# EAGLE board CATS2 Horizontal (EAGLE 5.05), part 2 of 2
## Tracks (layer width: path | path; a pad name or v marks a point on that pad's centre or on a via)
+5V  (via drill 0.51)
  Top 0.18: v86,58 85.73,57.73 IC49.3 85.73,52.73 84,51 79,51 78,50 78,43 74,39 68,39 | v382,58 384.95,58 R56.2 | IC13.3 373.73,57.73 v374,58 | R40.2 354.95,58.05 v355,58 | IC9.3 347.73,57.73 v348,58 | 332.26,56 IC7.6 | 332.26,56 332.26,57.74 v332,58 | IC7.8 327.18,55.18 328,56 332.26,56 | R67.2 309.95,58.05 v310,58 | IC17.3 301.73,57.73 v302,58 | R82.2 282.95,58.05 v283,58 | IC21.3 274.73,57.73 v275,58 | R97.2 255.95,58.05 v256,58 | IC25.3 247.73,57.73 v248,58 | R112.2 228.95,58.05 v229,58 | IC29.3 220.73,57.73 v221,58 | R127.2 201.95,58.05 v202,58 | IC33.3 193.73,57.73 v194,58 | R142.2 174.95,58.05 v175,58 | IC37.3 166.73,57.73 v167,58 | R157.2 147.95,58.05 v148,58 | IC41.3 139.73,57.73 v140,58 | R172.2 120.95,58.05 v121,58 | IC45.3 112.73,57.73 v113,58 | R187.2 94.05,58.05 v94,58 | 30,98.05 C19.2 | 30,98.05 R27.2 | 30,98.05 30.05,98 IC5.2 30.87,90.13 33,88 v45,88 | IC2.6 55.27,39.73 56,39 68,39 | 68,39 v69,39
  Bottom 0.18: v86,58 v94,58 v113,58 v121,58 v140,58 v148,58 v167,58 v175,58 v194,58 v202,58 v221,58 v229,58 v248,58 v256,58 v275,58 v283,58 v302,58 v310,58 v332,58 v348,58 v355,58 v374,58 v382,58 | v45,88 69,64 v69,39
+12V  (via drill 0.71)
  Top 0.4: R62.1 368,99 367,100 v367,107 | R195.1 80,99 79,100 | 79,100 v79,107 | R180.1 107,99 106,100 v106,107 | R165.1 134,99 133,100 v133,107 | R150.1 161,99 160,100 v160,107 | R135.1 188,99 187,100 v187,107 | R120.1 215,99 214,100 v214,107 | R105.1 242,99 241,100 v241,107 | R90.1 269,99 268,100 v268,107 | R75.1 296,99 295,100 v295,107 | R47.1 337,99 336,100 v336,107 | 82.24,65.19 C95.1 84.95,64.95 IC50.8 | IC46.8 109.24,65.19 C88.1 | IC34.8 190.24,65.19 C67.1 | IC30.8 217.24,65.19 C60.1 | IC26.8 244.24,65.19 C53.1 | IC22.8 271.24,65.19 C46.1 | IC18.8 298.24,65.19 C39.1 | IC10.8 343.24,65.19 C30.1 | IC14.8 370.24,65.19 C38.1 | C74.1 165.95,64.95 IC38.8 | C81.1 138.95,64.95 IC42.8 | v79,91 79,100 | 73.86,45.24 C9.1 72.69,46.31 72,47 v67,47 | 73.86,45.24 PWR1.+VIN | 42,70 42,74 41,75 R18.2 41,74.95 41,74 40.73,73.73 IC4.3 34.27,73.73 | 42,70 R19.2 | C16.1 32.05,70.6 IC4.16 | IC4.16 31.19,71.19 30,70 28,70 27,71 27,71.95 R20.2 | Q3.3 Q4.3 25,77.73 25,76 | 25,76 29,76 30,75 IC4.13 33,75 34.27,73.73 | IC4.16 33.19,71.19 34,72 34,73.46 34.27,73.73 | C17.1 PWR2.+VIN | C17.1 | D3.3 25.07,112.8 C15.POS F1.1A 22,108 25,105 | 25,105 25,99 26,98 26.05,98.05 C18.1 27,96.25 IC5.3 27.54,95.54 26,94 26,87 24,85 19,85 18,84 18,75 | C17.1 26.05,106.05 25,105 | RLY1.3 7.19,76.81 9,75 18,75 | 18,75 24,75 25,76 | AUD2.+ 27.62,32.62 35,40 41.95,40 R8.2 42,43.95 R5.2 v44,44 | 73.86,45.24 73.86,60.86 v78,65 | 53,47.95 53.05,47.95 v54,47 | 53,47.95 C12.1 | 42,70 42,65 v43,64 | v46,64 R24.2 | 51.27,51.27 IC3.8 51.3,51 54,51 54,48.95 53,47.95
  Bottom 0.4: v79,107 v106,107 v133,107 v160,107 v187,107 v214,107 v241,107 v268,107 v295,107 v336,107 v367,107 | 301,64 300,63 275,63 274.19,63.81 IC22.8 274,65 274,64 273,63 248,63 247.19,63.81 IC26.8 247,65 247,64 246,63 221,63 220.19,63.81 IC30.8 220,65 220,64 219,63 194,63 193.19,63.81 IC34.8 193,65 193,64 192,63 167,63 166.19,63.81 IC38.8 166,65 166,64 165,63 140,63 139.19,63.81 IC42.8 139,65 139,64 138,63 113,63 112.19,63.81 IC46.8 112,65 112,64 111,63 86,63 85.19,63.81 IC50.8 80.81,65.19 79.5,66.5 | 301,64 301,65 IC18.8 | 301,64 302,63 345,63 346.19,64.19 IC10.8 346.19,63.81 347,63 372,63 373,64 373,65 IC14.8 | 79.5,66.5 79,67 v79,91 | 79.5,66.5 v78,65 | v67,47 v54,47 54,45 53,44 v44,44 43,45 v43,64 v46,64
+12VA  (via drill 0.71)
  Top 0.4: IC48.8 96.81,32.95 C98.1 95.95,33 95,33 v94,32 94,30.5 89.5,26 PWR1.+VOUT 75.08,24.42 76,23.5 C6.POS 72.75,22.2 R4.1 71.95,16.95 70,15 62,15 v55.5,21.5 | IC44.8 123.81,32.95 C91.1 121.95,32.95 v121,32 | IC40.8 150.81,32.95 C84.1 148.95,32.95 v148,32 | IC36.8 177.81,32.95 C77.1 175.95,32.95 v175,32 | IC32.8 204.81,32.95 C70.1 202.95,32.95 v202,32 | IC28.8 231.81,32.95 C63.1 229.95,32.95 v229,32 | IC24.8 258.81,32.95 C56.1 256.95,32.95 v256,32 | IC20.8 285.81,32.95 C49.1 283.95,32.95 v283,32 | IC16.8 312.81,32.95 C42.1 310.95,32.95 v310,32 | IC6.8 359.81,32.95 C25.1 357.95,32.95 v357,32 | IC11.8 384.81,32.95 C33.1 382.95,32.95 v382,32 | C4.1 44.09,20 IC1.5 44.37,20.86 45,21.5 v50,21.5
  Bottom 0.4: v94,32 v121,32 v148,32 v175,32 v202,32 v229,32 v256,32 v283,32 v310,32 v357,32 v382,32 | v55.5,21.5 v50,21.5
+12VB  (via drill 0.51)
  Top 0.18: v86,40 85.73,40.27 IC49.6 85.73,45.27 85,46 82,46 79.75,43.75 79.75,34 77,34 70.05,27.05 R4.2 66.8,23 C3.POS 65.8,22 64,22 59,27 59,32 56,32 55.27,31.27 IC2.3 | v389,40 389,42.73 IC12.3 | IC45.6 112.73,40.27 v113,40 | IC41.6 139.73,40.27 v140,40 | IC37.6 166.73,40.27 v167,40 | IC33.6 193.73,40.27 v194,40 | IC29.6 220.73,40.27 v221,40 | IC47.3 101.27,40.27 v101,40 | IC43.3 128.27,40.27 v128,40 | IC39.3 155.27,40.27 v155,40 | IC35.3 182.27,40.27 v182,40 | IC31.3 209.27,40.27 v209,40 | IC27.3 236.27,40.27 v236,40 | IC25.6 247.73,40.27 v248,40 | IC23.3 263.27,40.27 v263,40 | IC21.6 274.73,40.27 v275,40 | IC19.3 290.27,40.27 v290,40 | IC17.6 301.73,40.27 v302,40 | IC15.3 317.27,40.27 v317,40 | IC9.6 347.73,40.27 v348,40 | IC8.3 362.27,40.27 v362,40 | IC13.6 373.73,40.27 v374,40
  Bottom 0.18: v86,40 v101,40 v113,40 v128,40 v140,40 v155,40 v167,40 v182,40 v194,40 v209,40 v221,40 v236,40 v248,40 v263,40 v275,40 v290,40 v302,40 v317,40 v348,40 v362,40 v374,40 v389,40
+15V  (via drill 0.71)
  Top 0.4: C20.POS 71,108.55 PWR2.+VOUT 73.5,104.5 v74,104
  Bottom 0.4: J36.1 J33.1 J30.1 J27.1 J24.1 J21.1 J18.1 J15.1 J9.1 J12.1 | J39.1 92.9,94.5 76.5,94.5 74,97 v74,104
  Bottom 0.406: J36.1 J39.1
-8V  (via drill 0.51)
  Top 0.18: v367,55 IC8.5 | v322,55 IC15.5 | v295,55 IC19.5 | v268,55 IC23.5 | v241,55 IC27.5 | IC31.5 v214,55 | v187,55 IC35.5 | v160,55 IC39.5 | v133,55 IC43.5 | v106,55 IC47.5 103.81,113.19 100.75,116.25 77.75,116.25 75,119 59,119 57,117 57,114.09 D5.1 R28.1 55,111 54.2,111.8 C22.POS | IC12.5 392,54.81 v392,52
  Bottom 0.18: v392,52 392,54 391,55 v367,55 v322,55 v295,55 v268,55 v241,55 v214,55 v187,55 v160,55 v133,55 v106,55
-15V  (via drill 0.71)
  Top 0.4: PWR2.-VOUT 73.19,90.81 70,94 70,97.47 PWR2.TRM | C21.NEG 64,116 62,114 62,112 61,111 | 61,111 R28.2 | PWR2.TRM 70.03,100.97 61,110 61,111 | v76,99 75.47,99 PWR2.TRM
  Bottom 0.4: v76,99 77.74,97.26 J39.2 J36.2 J33.2 J30.2 J27.2 J24.2 J21.2 J18.2 J15.2 J9.2 J12.2
AGND
  pour Top (rank 2): 7,0 32,0 32,28 46,28 46,36 78.5,36 78.5,49 395,49 395,121 0,121 0,75 4,75 4,56 7,56
  pour Bottom (rank 2): 0,0 32,0 32,28 46,28 46,36 78.5,36 78.5,49 395,49 395,121 0,121
DRIVE  (via drill 0.51)
  Top 0.18: v101,81 D38.3 | v389,79 D10.3 | v362,81 D8.3 | v317,81 D14.3 | v290,81 D17.3 | v263,81 D20.3 | v236,81 D23.3 | v209,81 D26.3 | v182,81 D29.3 | v155,81 D32.3 | v128,81 D35.3 | D2.3 46.73,70.73 v57,81 v89,81
  Bottom 0.18: v389,79 387,81 v362,81 v317,81 v290,81 v263,81 v236,81 v209,81 v182,81 v155,81 v128,81 v101,81 v89,81 | J4.7 11.63,103.37 19,96 42,96 v57,81
GND
  pour Top: 33,0 395,0 395,48 79.5,48 79.5,35 47,35 47,27 33,27
  pour Bottom: 33,0 395,0 395,48 79.5,48 79.5,35 47,35 47,27 33,27
N$1
  Top 0.18: R21.1 R23.2 54,61.05 54,62 52.05,63.95 Q2.1
N$2
  Top 0.18: IC3.1 51.27,57.27 52,58 52,58.95 | 52,58.95 R21.2 | 52,58.95 50,58.95 C11.2
N$3
  Top 0.18: Q5.1 57.17,61 56,61 55,62 55,66 54.73,66.27 Q2.3 51.27,66.27 50,65 50,64.05 R24.1
N$4
  Top 0.18: R22.2 47,67 45,65 45,63 47,61 R15.2 C11.1 48,58.95 48,58 50,56 IC3.2
N$5
  Top 0.18: J9.6 340.38,95.89 D9.3
N$6
  Top 0.18: R47.2 347.21,99 J9.7
N$7
  Top 0.18: D7.1 339.05,103.95 341,102 341,101.05 R48.2 347.21,101 J9.8
N$8
  Top 0.18: J5.CONDUCTOR 22,9 21,8 R30.1
N$9
  Top 0.18: D3.1 28.05,116.95 29,116 29,111.27 D4.3
N$10
  Top 0.18: D2.1 45.95,75 R16.2
N$11
  Top 0.18: Q1.3 39.73,76.73 39,76 | 39,76 39,75.05 R18.1 | IC4.11 33.46,77.54 34.73,76.27 IC4.5 38.73,76.27 39,76
N$12
  Top 0.18: IC4.6 35.46,77.54 34,79 34,80 33,81 27,81 Q3.1
N$13
  Top 0.18: R20.1 C14.2 29.22,73.73 IC4.14
N$14
  Top 0.18: IC4.2 38.59,72.46 C13.2 R19.1
N$15
  Top 0.18: Q4.1 28.05,77.05 29.81,78.81 IC4.10
N$16  (via drill 0.51)
  Top 0.18: Q4.2 27.95,78.95 v29,80
  Bottom 0.18: v29,80 12,63 12,56.72 AUD1.+
N$17
  Top 0.18: R25.1 21.05,79.59 TP.1
N$18
  Top 0.18: Q3.2 23,82.95 R25.2
N$19
  Top 0.18: J2.CONDUCTOR R7.1
N$20  (via drill 0.51)
  Top 0.18: 7.19,82.81 RLY1.1 7.11,82 5,82 | J4.3 7,102 1,96 1,86 5,82 | Q5.2 60,65.92 60,67 59,68 51,68 50,67 R22.1 49.95,68.05 49,69 47,69 44,66 44,63 43,62 42,62 37,67 v7,67 | v3,81 4,81 5,82
  Bottom 0.18: v7,67 7,77 v3,81
N$21
  Top 0.18: J12.5 382.52,105.48 388,100 388,82 384,78 384,76.05 R61.1
N$22
  Top 0.18: IC8.6 362,55.27 C27.2 R41.2
N$23
  Top 0.18: IC14.1 382.07,65.19 R199.CW 388.66,62.46 R199.W 391.2,65.8 388,69 388,70 D10.1 388,70.09 388,71 385.95,73.05 R61.2
N$24
  Top 0.18: R16.1 R17.2 42.05,76.95 Q1.1
N$25  (via drill 0.51)
  Top 0.18: C37.1 383,70 380.81,67.81 IC14.2 380.54,68 379,68 | R57.1 R56.1 383.05,59.95 378,65 378,67 379,68 | R58.2 377.95,69.05 379,68 | v374,78 R59.2
  Bottom 0.18: v374,78 375.95,78 R58.2 377.95,69.05 379,68 380.54,68 IC14.2
N$26
  Top 0.18: J12.3 383,100 387,96 387,84 386,83 381,83 376,78 376,76.05 R58.1 373.19,73.14 IC14.5 371,75 C102.2
N$27
  Top 0.18: R199.CCW 384.7,67.7 386,69 386,69.95 C37.2
N$28
  Top 0.18: C34.2 385.73,25.32 IC11.1 385.73,29.73 386.25,30.25 390.25,30.25 391,31 391,35 387,39 387,42.73 IC12.2
N$29
  Top 0.18: R29.2 17.05,5.05 D6.1 17,5 17,6 Q6.1
N$30
  Top 0.18: R26.2 33,96.25 IC5.1
N$31
  Bottom 0.4: F1.2A 22,88 12,98 10.53,98 J4.9
N$32
  Top 0.18: J15.5 310.52,105.48 316,100 316,82 312,78 312,76.05 R64.1
N$33
  Top 0.18: J10.CONDUCTOR R49.2
N$34
  Top 0.18: R49.1 R51.2 C32.2 380.05,15 381,15 389,23 389,26 388.27,26.73 IC11.3
N$35
  Top 0.18: R52.2 392,42.81 IC12.4 | C34.1 387.95,26.05 387,27 IC11.2 387,29 387.75,29.75 393.75,29.75 394,30 394,39 393,40 392.05,40 R52.2 | R52.2 391.95,40
N$36
  Top 0.18: C36.2 370.32,67.73 IC14.7 373.46,68 375,68 376,67 R55.2
N$37
  Top 0.18: R55.1 376,55.27 IC13.2
N$38
  Top 0.18: IC14.6 370.32,70.27 C36.1 369.95,69.95 368.25,68.25 368.25,59.75 370,58 370.95,58 R60.2 371,55.19 IC13.4
N$39
  Top 0.18: IC13.5 371.19,40.14 R54.2 371,39.95 372.05,39.95 376,36 388,36 389.54,34.46 IC11.5
N$40
  Top 0.18: R50.1 376,34 377,35 386,35 387,34 IC11.7 IC11.6
N$41
  Top 0.18: Q6.3 13,8 9,12 9,27.62 AUD2.-
N$42
  Top 0.18: J11.CONDUCTOR R50.2
N$43
  Top 0.18: J9.5 351.52,105.48 357,100 357,76.05 R46.1
N$44
  Top 0.18: R46.2 358.95,73.05 361,71 361,70.09 D8.1 361.05,68.95 364,66 364,65.2 R45.W 360.34,65 R45.CW 356.54,62.46 IC10.1
N$45  (via drill 0.51)
  Top 0.18: C29.1 356,70 353.81,67.81 IC10.2 352,67.73 | R41.1 R40.1 356.05,59.95 355,61 | 352,67.73 351.27,67.73 350,69 350,75.95 R42.2 | 355,61 351,65 351,66.73 352,67.73 | v346,77 R43.2 | R39.1 335.95,58.95 v338,61 | v353,61 355,61
  Bottom 0.18: v346,77 348.95,77 R42.2 349.95,69.05 351,68 353.54,68 IC10.2 | v338,61 v353,61
N$46
  Top 0.18: J9.3 352,100 356,96 356,84 355,83 353,83 348,78 348,76.05 R42.1 346.19,74.14 IC10.5 345,74 C31.2
N$47
  Top 0.18: C29.2 358.95,68.79 R45.CCW
N$48
  Top 0.18: D1.1 58.95,52.51 J3.1
N$49
  Top 0.18: R14.2 C10.2 R13.2 61,47 58,44 | IC2.5 57.81,43.81 58,44 | IC3.3 48.73,53.27 49,53 54,53 55,52 55,47 58,44
N$50
  Top 0.18: R10.2 C2.2 51,17.25 50.5,16.75 48.5,16.75 47.25,18 47.25,18.25 46.75,18.75 44.75,18.75 44.5,18.5 44.5,17.86 IC1.1
N$51
  Top 0.18: R10.1 53,29 52.73,29.27 IC2.2
N$52
  Top 0.18: J1.CONDUCTOR R1.2
N$53
  Top 0.18: R1.1 R2.2 C1.2 46.27,15.22 IC1.3
N$54
  Top 0.18: IC1.4 46.29,20.25 48,20.25 48.3,19.95 R3.2 C2.1 51,21 51.5,21.5 51.5,32 54,32 54,28 57,28 57.81,28.81 IC2.4
N$55
  Top 0.18: C26.2 360.73,25.32 IC6.1 360.73,29.73 361.25,30.25 365.25,30.25 366,31 366,34 362,38 361,38 360,39 360,42.73 IC8.2
N$56
  Top 0.18: C31.1 R43.1
N$57
  Top 0.18: J7.CONDUCTOR R32.2
N$58
  Top 0.18: R32.1 R34.2 C24.2 355.05,15 356,15 364,23 364,26 363.27,26.73 IC6.3
N$59
  Top 0.18: R35.2 365,42.81 IC8.4 | C26.1 362.95,26.05 362,27 IC6.2 362,29 362.75,29.75 366.75,29.75 367,30 367,39 366,40 365.05,40 R35.2 | R35.2 364.95,40
N$60
  Top 0.18: R6.W 45.85,47.8 C5.2 46,49 47.46,50.46 IC3.5
N$61
  Top 0.18: C28.2 343.95,69.05 345,68 345.92,68 IC10.7 346.46,68 348,68 350,66 R38.2
N$62
  Top 0.18: IC9.2 350.27,57.78 R38.1
N$63
  Top 0.18: IC10.6 345.92,70 345,70 344.05,70.95 C28.1 342.95,71 342,71 341,70 341,61 344,58 344.05,58.05 R44.2 345,55.19 IC9.4
N$64
  Top 0.18: IC9.5 345.19,40.14 R37.2 345,39.95 346.05,39.95 350,36 363,36 364.54,34.46 IC6.5
N$65
  Top 0.18: R33.1 351,34 352,35 361,35 362,34 IC6.7 IC6.6
N$66
  Top 0.18: J8.CONDUCTOR R33.2
N$67
  Top 0.18: R31.2 330,31 J6.CONDUCTOR
N$68
  Top 0.18: R31.1 330,44.33 IC7.2
N$69
  Top 0.18: IC7.3 332.26,32.74 333,32 333,30.54 J6.SHIELD1 333.5,29.96 333.5,29 333,28.5 329,28.5 328.46,29.04 J6.SHIELD2
N$70
  Top 0.18: R6.CW 38.46,45.59 R5.1
N$71
  Top 0.18: R39.2 335,53.83 IC7.5
N$72  (via drill 0.51)
  Top 0.18: 50,49.25 50,48.05 C7.1 R11.2 | 50,49.25 IC3.7 | v53,50 52.25,49.25 50,49.25
  Bottom 0.18: J3.2 57,56 53,52 v53,50
N$73
  Top 0.18: J12.6 371.38,95.89 D12.3
N$74
  Top 0.18: R62.2 378.21,99 J12.7
N$75
  Top 0.18: D11.1 370.05,103.95 372,102 372,101.05 R63.2 378.21,101 J12.8
N$76
  Top 0.18: R57.2 C35.2 389,55.27 IC12.6
N$77
  Top 0.18: R13.1 60.05,49.95 60,50 59,49 58.27,49 D1.3
N$78
  Top 0.18: IC3.6 48.73,49.73 48,49 48,48.05 C7.2 R11.1 48,45.95 48,45 44,41 R9.1
N$79
  Top 0.18: R36.2 357,42.81 IC8.1
N$80
  Top 0.18: R53.2 384,42.81 IC12.1
N$81  (via drill 0.51)
  Top 0.18: IC18.1 311.86,65.19 R66.1 | R64.2 313.95,71.05 315,70 316,70 | 316,70 D14.1 | v316,68 316,70
  Bottom 0.18: v316,68 313.19,65.19 IC18.1
N$82  (via drill 0.51)
  Top 0.18: C40.1 309.08,68 IC18.2 307.27,67.73 | R77.1 R67.1 311.05,59.95 306,65 306,66.46 307.27,67.73 | 307.27,67.73 306,69 306,75.95 R65.2 | v302,79 R200.2
  Bottom 0.18: v302,79 302.95,79 R65.2 305.95,69.05 307,68 308.54,68 IC18.2
N$83
  Top 0.18: J15.3 311,100 315,96 315,84 314,83 309,83 304,78 304,76.05 R65.1 301.19,73.14 IC18.5 298.95,75.05 C103.2
N$84
  Top 0.18: R66.2 C40.2
N$85
  Top 0.18: C43.2 313.73,25.32 IC16.1 313.73,29.73 314.25,30.25 318.25,30.25 319,31 319,35 315,39 315,42.73 IC15.2
N$86
  Top 0.18: J14.CONDUCTOR R68.2
N$87
  Top 0.18: R68.1 R69.2 C45.2 308.05,15 309,15 317,23 317,26 316.27,26.73 IC16.3
N$88
  Top 0.18: R70.2 320,42.81 IC15.4 | C43.1 315.95,26.05 315,27 IC16.2 315,29 315.75,29.75 321.75,29.75 322,30 322,39 321,40 320.05,40 R70.2 | R70.2 319.95,40
N$89
  Top 0.18: C44.2 298.32,67.73 IC18.7 301.46,68 303,68 304,67 R71.2
N$90
  Top 0.18: R71.1 304,55.27 IC17.2
N$91
  Top 0.18: IC18.6 298.32,70.27 C44.1 297.95,69.95 296.25,68.25 296.25,59.75 298,58 298.95,58 R72.2 299,55.19 IC17.4
N$92
  Top 0.18: IC17.5 299.19,40.14 R73.2 299,39.95 300.05,39.95 304,36 316,36 317.54,34.46 IC16.5
N$93
  Top 0.18: R74.1 304,34 305,35 314,35 315,34 IC16.7 IC16.6
N$94
  Top 0.18: J13.CONDUCTOR R74.2
N$95
  Top 0.18: D13.3 306.2,96.27 J15.6
N$96
  Top 0.18: R75.2 306.21,99 J15.7
N$97
  Top 0.18: D15.1 298.05,103.95 300,102 300,101.05 R76.2 306.21,101 J15.8
N$98
  Top 0.18: IC15.6 317.27,57.78 C41.2 R77.2
N$99
  Top 0.18: R78.2 312,42.81 IC15.1
N$100
  Top 0.18: J18.5 283.52,105.48 289,100 289,82 285,78 285,76.05 R79.1
N$101  (via drill 0.51)
  Top 0.18: IC22.1 284.86,65.19 R81.1 | R79.2 286.95,71.05 288,70 289,70 | 289,70 D17.1 | v289,68 289,70
  Bottom 0.18: v289,68 286.19,65.19 IC22.1
N$102  (via drill 0.51)
  Top 0.18: C47.1 284.78,67.73 IC22.2 280.27,67.73 | R92.1 R82.1 284.05,59.95 279,65 279,66.46 280.27,67.73 | 280.27,67.73 279,69 279,75.95 R80.2 | v275,79 R201.2
  Bottom 0.18: v275,79 275.95,79 R80.2 278.95,69.05 280,68 281.54,68 IC22.2
N$103
  Top 0.18: J18.3 284,100 288,96 288,84 287,83 282,83 277,78 277,76.05 R80.1 274.19,73.14 IC22.5 271.95,75.05 C104.2
N$104
  Top 0.18: R81.2 C47.2
N$105
  Top 0.18: C50.2 286.73,25.32 IC20.1 286.73,29.73 287.25,30.25 291.25,30.25 292,31 292,35 288,39 288,42.73 IC19.2
N$106
  Top 0.18: J17.CONDUCTOR R83.2
N$107
  Top 0.18: R83.1 R84.2 C52.2 281.05,15 282,15 290,23 290,26 289.27,26.73 IC20.3
N$108
  Top 0.18: R85.2 293,42.81 IC19.4 | C50.1 288.95,26.05 288,27 IC20.2 288,29 288.75,29.75 294.75,29.75 295,30 295,39 294,40 293.05,40 R85.2 | R85.2 292.95,40
N$109
  Top 0.18: C51.2 271.32,67.73 IC22.7 274.46,68 276,68 277,67 R86.2
N$110
  Top 0.18: IC21.2 277.27,57.78 R86.1
N$111
  Top 0.18: IC22.6 271.32,70.27 C51.1 270.95,69.95 269.25,68.25 269.25,59.75 271,58 271.95,58 R87.2 272.19,57.86 IC21.4
N$112
  Top 0.18: IC21.5 272.19,40.14 R88.2 272,39.95 273.05,39.95 277,36 289,36 290.54,34.46 IC20.5
N$113
  Top 0.18: R89.1 277,34 278,35 287,35 288,34 IC20.7 IC20.6
N$114
  Top 0.18: J16.CONDUCTOR R89.2
N$115
  Top 0.18: D16.3 279.2,96.27 J18.6
N$116
  Top 0.18: R90.2 279.21,99 J18.7
N$117
  Top 0.18: D18.1 271.05,103.95 273,102 273,101.05 R91.2 279.21,101 J18.8
N$118
  Top 0.18: IC19.6 290.27,57.78 C48.2 R92.2
N$119
  Top 0.18: R93.2 285,42.81 IC19.1
N$120
  Top 0.18: J21.5 256.52,105.48 262,100 262,82 258,78 258,76.05 R94.1
N$121  (via drill 0.51)
  Top 0.18: IC26.1 257.86,65.19 R96.1 | R94.2 259.95,71.05 261,70 262,70 | 262,70 D20.1 | v262,68 262,70
  Bottom 0.18: v262,68 259.19,65.19 IC26.1
N$122  (via drill 0.51)
  Top 0.18: C54.1 257.78,67.73 IC26.2 253.27,67.73 | R107.1 R97.1 257.05,59.95 252,65 252,66.46 253.27,67.73 | 253.27,67.73 252,69 252,75.95 R95.2 | v248,79 R202.2
  Bottom 0.18: v248,79 248.95,79 R95.2 251.95,69.05 253,68 254.54,68 IC26.2
N$123
  Top 0.18: J21.3 257,100 261,96 261,84 260,83 255,83 250,78 250,76.05 R95.1 247.19,73.14 IC26.5 244.95,75.05 C105.2
N$124
  Top 0.18: R96.2 C54.2
N$125
  Top 0.18: C57.2 259.73,25.32 IC24.1 259.73,29.73 260.25,30.25 264.25,30.25 265,31 265,35 261,39 261,42.73 IC23.2
N$126
  Top 0.18: J20.CONDUCTOR R98.2
N$127
  Top 0.18: R98.1 R99.2 C59.2 254.05,15 255,15 263,23 263,26 262.27,26.73 IC24.3
N$128
  Top 0.18: R100.2 266,42.81 IC23.4 | C57.1 261.95,26.05 261,27 IC24.2 261,29 261.75,29.75 267.75,29.75 268,30 268,39 267,40 266.05,40 R100.2 | R100.2 265.95,40
N$129
  Top 0.18: C58.2 244.32,67.73 IC26.7 247.46,68 249,68 250,67 R101.2
N$130
  Top 0.18: IC25.2 250.27,57.78 R101.1
N$131
  Top 0.18: IC26.6 244.32,70.27 C58.1 243.95,69.95 242.25,68.25 242.25,59.75 244,58 244.95,58 R102.2 245,55.19 IC25.4
N$132
  Top 0.18: IC25.5 245.19,40.14 R103.2 245,39.95 246.05,39.95 250,36 262,36 263.54,34.46 IC24.5
N$133
  Top 0.18: R104.1 250,34 251,35 260,35 261,34 IC24.7 IC24.6
N$134
  Top 0.18: J19.CONDUCTOR R104.2
N$135
  Top 0.18: D19.3 252.2,96.27 J21.6
N$136
  Top 0.18: R105.2 252.21,99 J21.7
N$137
  Top 0.18: D21.1 244.05,103.95 246,102 246,101.05 R106.2 252.21,101 J21.8
N$138
  Top 0.18: IC23.6 263.27,57.78 C55.2 R107.2
N$139
  Top 0.18: R108.2 258,42.81 IC23.1
N$140
  Top 0.18: J24.5 229.52,105.48 235,100 235,82 231,78 231,76.05 R109.1
N$141  (via drill 0.51)
  Top 0.18: IC30.1 230.86,65.19 R111.1 | R109.2 232.95,71.05 234,70 235,70 | 235,70 D23.1 | v235,68 235,70
  Bottom 0.18: v235,68 232.19,65.19 IC30.1
N$142  (via drill 0.51)
  Top 0.18: C61.1 228.08,68 IC30.2 226.27,67.73 | R122.1 R112.1 230.05,59.95 225,65 225,66.46 226.27,67.73 | 226.27,67.73 225,69 225,75.95 R110.2 | v221,79 R203.2
  Bottom 0.18: v221,79 221.95,79 R110.2 224.95,69.05 226,68 227.54,68 IC30.2
N$143
  Top 0.18: J24.3 230,100 234,96 234,84 233,83 228,83 223,78 223,76.05 R110.1 220.19,73.14 IC30.5 217.95,75.05 C106.2
N$144
  Top 0.18: R111.2 C61.2
N$145
  Top 0.18: C64.2 232.73,25.32 IC28.1 232.73,29.73 233.25,30.25 237.25,30.25 238,31 238,35 234,39 234,42.73 IC27.2
N$146
  Top 0.18: J23.CONDUCTOR R113.2
N$147
  Top 0.18: R113.1 R114.2 C66.2 227.05,15 228,15 236,23 236,26 235.27,26.73 IC28.3
N$148
  Top 0.18: R115.2 239,42.81 IC27.4 | C64.1 234.95,26.05 234,27 IC28.2 234,29 234.75,29.75 240.75,29.75 241,30 241,39 240,40 239.05,40 R115.2 | R115.2 238.95,40
N$149
  Top 0.18: C65.2 217.32,67.73 IC30.7 220.46,68 222,68 223,67 R116.2
N$150
  Top 0.18: IC29.2 223.27,57.78 R116.1
N$151
  Top 0.18: IC30.6 217.32,70.27 C65.1 216.95,69.95 215.25,68.25 215.25,59.75 217,58 217.95,58 R117.2 218.19,57.86 IC29.4
N$152
  Top 0.18: IC29.5 218.19,40.14 R118.2 218,39.95 219.05,39.95 223,36 235,36 236.54,34.46 IC28.5
N$153
  Top 0.18: R119.1 223,34 224,35 233,35 234,34 IC28.7 IC28.6
N$154
  Top 0.18: J22.CONDUCTOR R119.2
N$155
  Top 0.18: D22.3 225.2,96.27 J24.6
N$156
  Top 0.18: R120.2 225.21,99 J24.7
N$157
  Top 0.18: D24.1 217.05,103.95 219,102 219,101.05 R121.2 225.21,101 J24.8
N$158
  Top 0.18: IC27.6 236.27,57.78 C62.2 R122.2
N$159
  Top 0.18: R123.2 231,42.81 IC27.1
N$160
  Top 0.18: J27.5 202.52,105.48 208,100 208,82 204,78 204,76.05 R124.1
N$161  (via drill 0.51)
  Top 0.18: IC34.1 203.86,65.19 R126.1 | R124.2 205.95,71.05 207,70 208,70 | 208,70 D26.1 | v208,68 208,70
  Bottom 0.18: v208,68 205.19,65.19 IC34.1
N$162  (via drill 0.51)
  Top 0.18: C68.1 201.08,68 IC34.2 199.27,67.73 | R137.1 R127.1 203.05,59.95 198,65 198,66.46 199.27,67.73 | 199.27,67.73 198,69 198,75.95 R125.2 | v194,79 R205.2
  Bottom 0.18: v194,79 195,79 198,76 198,69 199,68 200.54,68 IC34.2
N$163
  Top 0.18: J27.3 203,100 207,96 207,84 206,83 201,83 196,78 196,76.05 R125.1 193.19,73.14 IC34.5 190.95,75.05 C108.2
N$164
  Top 0.18: R126.2 C68.2
N$165
  Top 0.18: C71.2 205.73,25.32 IC32.1 205.73,29.73 206.25,30.25 210.25,30.25 211,31 211,35 207,39 207,42.73 IC31.2
N$166
  Top 0.18: J26.CONDUCTOR R128.2
N$167
  Top 0.18: R128.1 R129.2 C73.2 200.05,15 201,15 209,23 209,26 208.27,26.73 IC32.3
N$168
  Top 0.18: R130.2 212,42.81 IC31.4 | C71.1 207.95,26.05 207,27 IC32.2 207,29 207.75,29.75 213.75,29.75 214,30 214,39 213,40 212.05,40 R130.2 | R130.2 211.95,40
N$169
  Top 0.18: C72.2 190.32,67.73 IC34.7 193.46,68 195,68 196,67 R131.2
N$170
  Top 0.18: R131.1 196,55.27 IC33.2
N$171
  Top 0.18: IC34.6 190.32,70.27 C72.1 189.95,69.95 188.25,68.25 188.25,59.75 190,58 190.95,58 R132.2 191,55.19 IC33.4
N$172
  Top 0.18: IC33.5 191.19,40.14 R133.2 191,39.95 192.05,39.95 196,36 208,36 209.54,34.46 IC32.5
N$173
  Top 0.18: R134.1 196,34 197,35 206,35 207,34 IC32.7 IC32.6
N$174
  Top 0.18: J25.CONDUCTOR R134.2
N$175
  Top 0.18: D25.3 198.2,96.27 J27.6
N$176
  Top 0.18: R135.2 198.21,99 J27.7
N$177
  Top 0.18: D27.1 190.05,103.95 192,102 192,101.05 R136.2 198.21,101 J27.8
N$178
  Top 0.18: IC31.6 209.27,57.78 C69.2 R137.2
N$179
  Top 0.18: R138.2 204,42.81 IC31.1
N$180
  Top 0.18: J30.5 175.52,105.48 181,100 181,82 177,78 177,76.05 R139.1
N$181  (via drill 0.51)
  Top 0.18: R139.2 178.95,71.05 180,70 181,70 | R141.1 174,65 IC38.1 | 181,70 D29.1 | v181,68 181,70
  Bottom 0.18: v181,68 178.19,65.19 IC38.1
N$182  (via drill 0.51)
  Top 0.18: C75.1 176.78,67.73 IC38.2 172.27,67.73 | R152.1 R142.1 176.05,59.95 171,65 171,66.46 172.27,67.73 | 172.27,67.73 171,69 171,75.95 R140.2 | v167,79 R204.2
  Bottom 0.18: v167,79 167.95,79 R140.2 170.95,69.05 172,68 173.54,68 IC38.2
N$183
  Top 0.18: J30.3 176,100 180,96 180,84 179,83 174,83 169,78 169,76.05 R140.1 166.19,73.14 IC38.5 163.95,75.05 C107.2
N$184
  Top 0.18: R141.2 C75.2
N$185
  Top 0.18: C78.2 178.73,25.32 IC36.1 178.73,29.73 179.25,30.25 183.25,30.25 184,31 184,35 180,39 180,42.73 IC35.2
N$186
  Top 0.18: J29.CONDUCTOR R143.2
N$187
  Top 0.18: R143.1 R144.2 C80.2 173.05,15 174,15 182,23 182,26 181.27,26.73 IC36.3
N$188
  Top 0.18: R145.2 185,42.81 IC35.4 | C78.1 180.95,26.05 180,27 IC36.2 180,29 180.75,29.75 186.75,29.75 187,30 187,39 186,40 185.05,40 R145.2 | R145.2 184.95,40
N$189
  Top 0.18: C79.2 163.32,67.73 IC38.7 166.46,68 168,68 169,67 R146.2
N$190
  Top 0.18: R146.1 169,55.27 IC37.2
N$191
  Top 0.18: IC38.6 163.32,70.27 C79.1 162.95,69.95 161.25,68.25 161.25,59.75 163,58 163.95,58 R147.2 164,55.19 IC37.4
N$192
  Top 0.18: IC37.5 164.19,40.14 R148.2 164,39.95 165.05,39.95 169,36 181,36 182.54,34.46 IC36.5
N$193
  Top 0.18: R149.1 169,34 170,35 179,35 180,34 IC36.7 IC36.6
N$194
  Top 0.18: J28.CONDUCTOR R149.2
N$195
  Top 0.18: D28.3 171.2,96.27 J30.6
N$196
  Top 0.18: R150.2 171.21,99 J30.7
N$197
  Top 0.18: D30.1 163.05,103.95 165,102 165,101.05 R151.2 171.21,101 J30.8
N$198
  Top 0.18: IC35.6 182,55.27 C76.2 R152.2
N$199
  Top 0.18: R153.2 177,42.81 IC35.1
N$200
  Top 0.18: J33.5 148.52,105.48 154,100 154,82 150,78 150,76.05 R154.1
N$201  (via drill 0.51)
  Top 0.18: IC42.1 149.86,65.19 R156.1 | R154.2 151.95,71.05 153,70 154,70 | 154,70 D32.1 | v154,68 154,70
  Bottom 0.18: v154,68 151.19,65.19 IC42.1
N$202  (via drill 0.51)
  Top 0.18: C82.1 147.08,68 IC42.2 145.27,67.73 | R167.1 R157.1 149.05,59.95 144,65 144,66.46 145.27,67.73 | 145.27,67.73 144,69 144,75.95 R155.2 | v140,79 R206.2
  Bottom 0.18: v140,79 140.95,79 R155.2 143.95,69.05 145,68 146.54,68 IC42.2
N$203
  Top 0.18: J33.3 149,100 153,96 153,84 152,83 147,83 142,78 142,76.05 R155.1 139.19,73.14 IC42.5 136.95,75.05 C109.2
N$204
  Top 0.18: R156.2 C82.2
N$205
  Top 0.18: C85.2 151.73,25.32 IC40.1 151.73,29.73 152.25,30.25 156.25,30.25 157,31 157,35 153,39 153,42.73 IC39.2
N$206
  Top 0.18: J32.CONDUCTOR R158.2
N$207
  Top 0.18: R158.1 R159.2 C87.2 146.05,15 147,15 155,23 155,26 154.27,26.73 IC40.3
N$208
  Top 0.18: R160.2 158,42.81 IC39.4 | C85.1 153.95,26.05 153,27 IC40.2 153,29 153.75,29.75 159.75,29.75 160,30 160,39 159,40 158.05,40 R160.2 | R160.2 157.95,40
N$209
  Top 0.18: C86.2 137.95,68.05 138,68 138.92,68 IC42.7 139.46,68 141,68 142,67 R161.2
N$210
  Top 0.18: R161.1 142,55.27 IC41.2
N$211
  Top 0.18: IC42.6 138.87,69.95 C86.1 135.95,69.95 134.25,68.25 134.25,59.75 136,58 136.95,58 R162.2 137,55.19 IC41.4
N$212
  Top 0.18: IC40.5 155.54,34.46 154,36 142,36 138.05,39.95 137.47,39.95 137.19,40.24 | R163.2 137.19,40.24 | 137.19,40.24 IC41.5
N$213
  Top 0.18: R164.1 142,34 143,35 152,35 153,34 IC40.7 IC40.6
N$214
  Top 0.18: J31.CONDUCTOR R164.2
N$215
  Top 0.18: D31.3 144.2,96.27 J33.6
N$216
  Top 0.18: R165.2 144.21,99 J33.7
N$217
  Top 0.18: D33.1 136.05,103.95 138,102 138,101.05 R166.2 144.21,101 J33.8
N$218
  Top 0.18: IC39.6 155.27,57.78 C83.2 R167.2
N$219
  Top 0.18: R168.2 150,42.81 IC39.1
N$220
  Top 0.18: J36.5 121.52,105.48 127,100 127,82 123,78 123,76.05 R169.1
N$221  (via drill 0.51)
  Top 0.18: IC46.1 122.86,65.19 R171.1 | R169.2 124.95,71.05 126,70 127,70 | 127,70 D35.1 | v127,68 127,70
  Bottom 0.18: v127,68 124.19,65.19 IC46.1
N$222  (via drill 0.51)
  Top 0.18: C89.1 122.78,67.73 IC46.2 118.27,67.73 | R182.1 R172.1 122.05,59.95 117,65 117,66.46 118.27,67.73 | 118.27,67.73 117,69 117,75.95 R170.2 | v113,79 R207.2
  Bottom 0.18: v113,79 113.95,79 R170.2 116.95,69.05 118,68 119.54,68 IC46.2
N$223
  Top 0.18: J36.3 122,100 126,96 126,84 125,83 120,83 115,78 115,76.05 R170.1 115.05,75.67 IC46.5 109.95,75.05 C110.2
N$224
  Top 0.18: R171.2 C89.2
N$225
  Top 0.18: C92.2 124.73,25.32 IC44.1 124.73,29.73 125.25,30.25 129.25,30.25 130,31 130,35 126,39 126,42.73 IC43.2
N$226
  Top 0.18: J35.CONDUCTOR R173.2
N$227
  Top 0.18: R173.1 R174.2 C94.2 119.05,15 120,15 128,23 128,26 127.27,26.73 IC44.3
N$228
  Top 0.18: R175.2 131,42.81 IC43.4 | C92.1 126.95,26.05 126,27 IC44.2 126,29 126.75,29.75 132.75,29.75 133,30 133,39 132,40 131.05,40 R175.2 | R175.2 130.95,40
N$229
  Top 0.18: C93.2 109.32,67.73 IC46.7 112.46,68 114,68 115,67 R176.2
N$230
  Top 0.18: R176.1 115,55.27 IC45.2
N$231
  Top 0.18: IC46.6 109.32,70.27 C93.1 108.95,69.95 107.25,68.25 107.25,59.75 109,58 109.95,58 R177.2 110.19,57.86 IC45.4
N$232
  Top 0.18: IC44.5 128.54,34.46 127,36 115,36 111.05,39.95 110,39.95 R178.2 110.19,40.24 IC45.5
N$233
  Top 0.18: R179.1 115,34 116,35 125,35 126,34 IC44.7 IC44.6
N$234
  Top 0.18: J34.CONDUCTOR R179.2
N$235
  Top 0.18: D34.3 117.2,96.27 J36.6
N$236
  Top 0.18: R180.2 117.21,99 J36.7
N$237
  Top 0.18: D36.1 109.05,103.95 111,102 111,101.05 R181.2 117.21,101 J36.8
N$238
  Top 0.18: IC43.6 128.27,57.78 C90.2 R182.2
N$239
  Top 0.18: R183.2 123,42.81 IC43.1
N$240
  Top 0.18: J39.5 94.52,105.48 100,100 100,82 96,78 96,76.05 R184.1
N$241  (via drill 0.51)
  Top 0.18: R184.2 97.95,71.05 99,70 100,70 D38.1 100.05,68.05 v100,68 | R186.1 93,65 IC50.1
  Bottom 0.18: v100,68 97.19,65.19 IC50.1
N$242  (via drill 0.51)
  Top 0.18: C96.1 93.08,68 IC50.2 91.27,67.73 | R197.1 R187.1 95.05,59.95 90,65 90,66.46 91.27,67.73 | 91.27,67.73 90,69 90,75.95 R185.2 | v86,79 R208.2
  Bottom 0.18: v86,79 86.95,79 R185.2 89.95,69.05 91,68 92.54,68 IC50.2
N$243
  Top 0.18: J39.3 95,100 99,96 99,84 98,83 93,83 88,78 88,76.05 R185.1 88.05,75.67 IC50.5 82.95,75.05 C111.2
N$244
  Top 0.18: R186.2 C96.2
N$245
  Top 0.18: C99.2 97.73,25.32 IC48.1 97.73,29.73 98.25,30.25 102.25,30.25 103,31 103,35 99,39 99,42.73 IC47.2
N$246
  Top 0.18: J38.CONDUCTOR R188.2
N$247
  Top 0.18: R188.1 R189.2 C101.2 92.05,15 93,15 101,23 101,26 100.27,26.73 IC48.3
N$248
  Top 0.18: R190.2 104,42.81 IC47.4 | C99.1 99.95,26.05 99,27 IC48.2 99,29 99.75,29.75 105.75,29.75 106,30 106,39 105,40 104.05,40 R190.2 | R190.2 103.95,40
N$249
  Top 0.18: C100.2 82.32,67.73 IC50.7 85.46,68 87,68 88,67 R191.2
N$250
  Top 0.18: IC49.2 88.27,57.78 R191.1
N$251
  Top 0.18: IC50.6 82.32,70.27 C100.1 80.25,68.2 80.25,59.75 82,58 82.95,58 R192.2 83.19,57.86 IC49.4
N$252
  Top 0.18: IC48.5 101.54,34.46 100,36 88,36 84.05,39.95 83,39.95 R193.2 83.19,40.24 IC49.5
N$253
  Top 0.18: R194.1 88,34 89,35 98,35 99,34 IC48.7 IC48.6
N$254
  Top 0.18: J37.CONDUCTOR R194.2
N$255
  Top 0.18: D37.3 90.2,96.27 J39.6
N$256
  Top 0.18: R195.2 90.21,99 J39.7
N$257
  Top 0.18: D39.1 82.05,103.95 84,102 84,101.05 R196.2 90.21,101 J39.8
N$258
  Top 0.18: IC47.6 101.27,57.78 C97.2 R197.2
N$259
  Top 0.18: R198.2 96,42.81 IC47.1
N$260
  Top 0.18: C102.1 R59.1
N$261
  Top 0.18: C103.1 R200.1
N$262
  Top 0.18: C104.1 R201.1
N$263
  Top 0.18: C105.1 R202.1
N$264
  Top 0.18: C106.1 R203.1
N$265
  Top 0.18: C107.1 R204.1
N$266
  Top 0.18: C108.1 R205.1
N$267  (via drill 0.51)
  Top 0.18: IC13.1 378.81,53.19 v380,52
  Bottom 0.18: v380,52 380,49 378,47 376.3,47 D40.A
N$268
  Top 0.18: C109.1 R206.1
N$269
  Top 0.18: C110.1 R207.1
N$270
  Top 0.18: C111.1 R208.1
N$271  (via drill 0.51)
  Top 0.18: IC17.1 306.81,53.19 v308,52
  Bottom 0.18: v308,52 308,49 306,47 304.3,47 D41.A
N$272  (via drill 0.51)
  Top 0.18: IC9.1 352.81,53.19 v354,52
  Bottom 0.18: v354,52 354,48 353,47 351.3,47 D42.A
N$273  (via drill 0.51)
  Top 0.18: IC21.1 279.81,53.19 v281,52
  Bottom 0.18: v281,52 281,49 279,47 277.3,47 D43.A
N$274  (via drill 0.51)
  Top 0.18: IC25.1 252.81,53.19 v254,52
  Bottom 0.18: v254,52 254,49 252,47 250,47 D44.A
N$275  (via drill 0.51)
  Top 0.18: IC33.1 198.81,53.19 v200,52
  Bottom 0.18: v200,52 200,49 198,47 196.3,47 D45.A
N$276  (via drill 0.51)
  Top 0.18: IC37.1 171.81,53.19 v173,52
  Bottom 0.18: v173,52 173,49 171,47 169.3,47 D46.A
N$277  (via drill 0.51)
  Top 0.18: IC29.1 225.81,53.19 v227,52
  Bottom 0.18: v227,52 227,49 225,47 223.3,47 D47.A
N$278  (via drill 0.51)
  Top 0.18: IC45.1 117.81,53.19 v119,52
  Bottom 0.18: v119,52 119,49 117,47 115.3,47 D48.A
N$279  (via drill 0.51)
  Top 0.18: IC41.1 144.81,53.19 v146,52
  Bottom 0.18: v146,52 146,49 144,47 142.3,47 D49.A
N$280  (via drill 0.51)
  Top 0.18: IC49.1 90.81,53.19 v92,52
  Bottom 0.18: v92,52 92,49 90,47 88.3,47 D50.A
TEMP  (via drill 0.51)
  Top 0.18: v83,108 D39.3 82.73,106.27 | v110,108 D36.3 | v137,108 D33.3 | D30.3 v164,108 | v191,108 D27.3 | v218,108 D24.3 | v245,108 D21.3 | v272,108 D18.3 | v299,108 D15.3 | v340,108 D7.3 | v371,108 D11.3 | D6.3 19.73,2.73 21,4 R30.2 21,5 21.05,5.05 C23.1 23.05,5 23,4.95 23,3 24.25,1.75 28.75,1.75 30.25,3.25 30.25,9.75 20,20 20,33 8,45 8,57 5,60 5,75 4,76 4,79 5,80 10,80 11,81 11,84 10,85 3,85 2,86 2,93 3,94 8,94 9,95 9,100 9.63,100.63 J4.8
  Bottom 0.18: v371,108 v340,108 v299,108 v272,108 v245,108 v218,108 v191,108 v164,108 v137,108 v110,108 v83,108 74,108 66,100 19,100 11,108 9,108 9,102.05 J4.8
V-DS  (via drill 0.51)
  Top 0.18: 370.05,92.05 D12.1 | v339,92 339,94 | 298.05,92.05 D13.1 | 271.05,92.05 D16.1 | 244.05,92.05 D19.1 | 217.05,92.05 D22.1 | 190.05,92.05 D25.1 | 163.05,92.05 D28.1 | 136.05,92.05 D31.1 | 109.05,92.05 D34.1 | 82.05,92.05 D37.1 | R7.2 R8.1 R9.2 44.95,38.05 46,37 v72,37
  Top 0.4: v370,92 370.05,92.05 | 339,94 D9.1 | v298,92 298.05,92.05 | v271,92 271.05,92.05 | v244,92 244.05,92.05 | v217,92 217.05,92.05 | v190,92 190.05,92.05 | v163,92 163.05,92.05 | v136,92 136.05,92.05 | v109,92 109.05,92.05 | v82,92 82.05,92.05
  Bottom 0.18: v370,92 v339,92 v298,92 v271,92 v244,92 v217,92 v190,92 v163,92 v136,92 v109,92 v82,92 72,92 | J4.6 10.89,106.11 19,98 66,98 72,92 | 72,92 v72,37

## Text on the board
Top: CH-11 | CH-10 | CH-9 | CH-8 | CH-7 | CH-6 | CH-5 | CH-4 | CH-3 | MOT | Push | CATS2 - Cold Atoms Transfer System Rev:A | University of Toronto - Physics
Target: CATS2 - Cold Atoms Transfer | System - Horizontal | J.Thywissen Labs | A. Stummer Nov 2009 | A1 | 0.18mm | 0.38mm | 0.18mm | 10m" | 1mm | Rev:A1 Nov'09 Original layout, Rev:A PCB.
